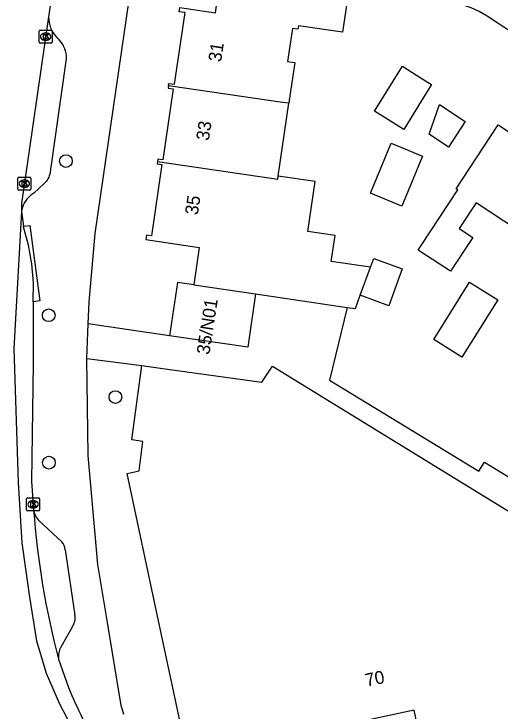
# Model space of a CAD drawing. Extents: x 159280 to 160375, y 384531 to 385872.
# Drawn here: x 159968.6 to 160006.1, y 384621.7 to 384675.4 of the extents above; entities that cross this region are included whole.
import ezdxf

# ---------------------------------------------------------------- set-up
doc = ezdxf.new("R2010")
doc.units = 0
for name, color, linetype in [('IMGEO_Boom', 7, 'Continuous'), ('IMGEO_Kolk', 7, 'Continuous'), ('IMGEO_Pand', 7, 'Continuous'), ('IMGEO_Pand_nummerreeks', 7, 'Continuous'), ('IMGEO_Rijbaan_lokaal_open', 7, 'Continuous'), ('IMGEO_Voetpad_open', 7, 'Continuous')]:
    doc.layers.add(name, color=color, linetype=linetype)

msp = doc.modelspace()

# ---------------------------------------------------------------- linework, layer by layer
at = {"layer": 'IMGEO_Boom'}
for centre in [(159972.645, 384664.044), (159971.323, 384652.191), (159976.457, 384645.896), (159971.332, 384640.849)]:
    msp.add_circle(centre, 0.489, dxfattribs=at)
at = {"layer": 'IMGEO_Kolk'}
for p, q in [((159970.586, 384673.196), (159970.586, 384674.048)), ((159970.661, 384674.122), (159971.513, 384674.122)), ((159971.074, 384673.902), (159971.099, 384673.902)), ((159971.587, 384674.048), (159971.587, 384673.196)), ((159971.097, 384673.342), (159971.072, 384673.342)), ((159971.513, 384673.122), (159970.661, 384673.122)), ((159968.947, 384661.888), (159968.947, 384662.74)), ((159969.022, 384662.814), (159969.874, 384662.814)), ((159969.435, 384662.594), (159969.46, 384662.594)), ((159969.948, 384662.74), (159969.948, 384661.888)), ((159969.874, 384661.814), (159969.022, 384661.814)), ((159969.458, 384662.034), (159969.433, 384662.034)), ((159969.619, 384637.219), (159969.619, 384638.071)), ((159969.694, 384638.145), (159970.546, 384638.145)), ((159970.107, 384637.925), (159970.132, 384637.925)), ((159970.62, 384638.071), (159970.62, 384637.219)), ((159970.546, 384637.145), (159969.694, 384637.145)), ((159970.13, 384637.365), (159970.105, 384637.365))]:
    msp.add_line(p, q, dxfattribs=at)
for points in [[(159970.586, 384673.196), (159970.586, 384674.048)], [(159970.661, 384674.122), (159971.513, 384674.122)], [(159971.587, 384674.048), (159971.587, 384673.196)], [(159970.907, 384673.822), (159971.03, 384673.822), (159971.03, 384673.671), (159971.16, 384673.822), (159971.324, 384673.822), (159971.178, 384673.671), (159971.331, 384673.422), (159971.179, 384673.422), (159971.094, 384673.586), (159971.03, 384673.519), (159971.03, 384673.422), (159970.907, 384673.422), (159970.907, 384673.822)], [(159971.513, 384673.122), (159970.661, 384673.122)], [(159968.947, 384661.888), (159968.947, 384662.74)], [(159969.022, 384662.814), (159969.874, 384662.814)], [(159969.948, 384662.74), (159969.948, 384661.888)], [(159969.268, 384662.514), (159969.391, 384662.514), (159969.391, 384662.363), (159969.521, 384662.514), (159969.685, 384662.514), (159969.539, 384662.363), (159969.692, 384662.114), (159969.54, 384662.114), (159969.455, 384662.278), (159969.391, 384662.211), (159969.391, 384662.114), (159969.268, 384662.114), (159969.268, 384662.514)], [(159969.874, 384661.814), (159969.022, 384661.814)], [(159969.619, 384637.219), (159969.619, 384638.071)], [(159969.694, 384638.145), (159970.546, 384638.145)], [(159970.62, 384638.071), (159970.62, 384637.219)], [(159969.94, 384637.845), (159970.063, 384637.845), (159970.063, 384637.694), (159970.193, 384637.845), (159970.357, 384637.845), (159970.211, 384637.694), (159970.364, 384637.445), (159970.212, 384637.445), (159970.127, 384637.609), (159970.063, 384637.542), (159970.063, 384637.445), (159969.94, 384637.445), (159969.94, 384637.845)], [(159970.546, 384637.145), (159969.694, 384637.145)]]:
    msp.add_lwpolyline(points, dxfattribs=at)
for centre, start, end in [((159970.663, 384674.046), 91.552, 178.448), ((159970.663, 384674.046), 91.552, 178.448), ((159971.511, 384674.046), 1.552, 88.448), ((159971.511, 384674.046), 1.552, 88.448), ((159970.663, 384673.198), 181.552, 268.448), ((159970.663, 384673.198), 181.552, 268.448), ((159971.511, 384673.198), 271.552, 358.448), ((159971.511, 384673.198), 271.552, 358.448), ((159969.024, 384662.738), 91.552, 178.448), ((159969.024, 384662.738), 91.552, 178.448), ((159969.872, 384662.738), 1.552, 88.448), ((159969.872, 384662.738), 1.552, 88.448), ((159969.024, 384661.89), 181.552, 268.448), ((159969.024, 384661.89), 181.552, 268.448), ((159969.872, 384661.89), 271.552, 358.448), ((159969.872, 384661.89), 271.552, 358.448), ((159969.696, 384638.069), 91.552, 178.448), ((159969.696, 384638.069), 91.552, 178.448), ((159970.544, 384638.069), 1.552, 88.448), ((159970.544, 384638.069), 1.552, 88.448), ((159969.696, 384637.221), 181.552, 268.448), ((159969.696, 384637.221), 181.552, 268.448), ((159970.544, 384637.221), 271.552, 358.448), ((159970.544, 384637.221), 271.552, 358.448)]:
    msp.add_arc(centre, 0.0765, start, end, dxfattribs=at)
for centre, major_axis, ratio, start_param, end_param in [((159971.073, 384673.622), (-0.387, 0.002), 0.722429, 4.712389, 7.853982), ((159971.098, 384673.622), (-0.39, 0.002), 0.717154, 1.570796, 4.712389), ((159969.434, 384662.314), (-0.387, 0.002), 0.722429, 4.712389, 7.853982), ((159969.459, 384662.314), (-0.39, 0.002), 0.717154, 1.570796, 4.712389), ((159970.106, 384637.645), (-0.387, 0.002), 0.722429, 4.712389, 7.853982), ((159970.131, 384637.645), (-0.39, 0.002), 0.717154, 1.570796, 4.712389)]:
    msp.add_ellipse(centre, major_axis=major_axis, ratio=ratio, start_param=start_param, end_param=end_param, dxfattribs=at)
at = {"layer": 'IMGEO_Pand'}
for points in [[(159980.544, 384669.845), (159980.57, 384670.023), (159981.011, 384669.958), (159981.816, 384675.472), (159981.365, 384675.538), (159981.412, 384675.862), (159984.161, 384675.46), (159984.655, 384678.84)], [(159994.441, 384677.412), (159993.938, 384673.964), (159990.537, 384674.46), (159990.497, 384674.19), (159990.075, 384674.251), (159989.703, 384671.7), (159990.264, 384671.618), (159989.864, 384668.879), (159989.811, 384668.513)], [(160000, 384668.646), (159998.656, 384666.483), (159996.401, 384667.885), (159998.545, 384671.335), (160000, 384670.43), (160000.8, 384669.933), (160000, 384668.646)], [(159980.544, 384669.845), (159980.518, 384669.663), (159980.911, 384669.606), (159980.112, 384664.133), (159979.715, 384664.191), (159979.689, 384664.015)], [(159989.811, 384668.513), (159989.305, 384668.561), (159980.544, 384669.845)], [(159988.991, 384662.895), (159989.811, 384668.513)], [(160002.095, 384665.124), (160000.602, 384666.105), (160001.403, 384668.402), (160003.391, 384667.095), (160002.095, 384665.124)], [(160008.441, 384658.06), (160004.227, 384660.831), (160002.927, 384658.854), (160003.958, 384658.177), (160002.244, 384655.571), (160000, 384657.047), (159999.772, 384657.197), (160000, 384657.544), (160002.817, 384661.828), (160002.678, 384661.92), (160003.166, 384662.661), (160005.913, 384666.838), (160008.828, 384664.921), (160010.181, 384666.978), (160013.061, 384665.084)], [(159998.497, 384660.591), (159996.09, 384661.585), (159997.675, 384665.424), (160000.082, 384664.43), (159998.497, 384660.591)], [(159979.689, 384664.015), (159979.664, 384663.84), (159980.038, 384663.786), (159979.237, 384658.295), (159978.846, 384658.352), (159978.796, 384658.009), (159982.908, 384657.409), (159982.484, 384654.527)], [(159979.689, 384664.015), (159988.45, 384662.731), (159988.956, 384662.653), (159988.991, 384662.895)], [(159996.093, 384655.883), (159993.067, 384656.324), (159993.359, 384658.324), (159991.266, 384658.629), (159991.828, 384662.482), (159988.991, 384662.895)], [(159996.093, 384655.883), (159996.338, 384656.551), (159998.534, 384655.747), (159997.499, 384652.918), (159995.303, 384653.722)], [(159995.303, 384653.722), (159996.093, 384655.883)], [(159982.484, 384654.527), (159981.227, 384654.712), (159980.624, 384650.612)], [(160003.709, 384654.731), (160005.884, 384653.378), (160003.134, 384648.957), (160000.959, 384650.31), (160003.709, 384654.731)], [(159982.484, 384654.527), (159987.248, 384653.826)], [(159987.248, 384653.826), (159986.645, 384649.726), (159980.624, 384650.612)], [(159987.248, 384653.826), (159994.3, 384652.788)], [(159994.3, 384652.788), (159994.927, 384652.696), (159995.303, 384653.722)], [(160011.237, 384634.358), (160011.297, 384634.075), (160011.515, 384633.037), (160011.69, 384632.205), (160012.697, 384632.417), (160013.12, 384630.406), (160015.037, 384630.809), (160016.519, 384623.743), (160017.106, 384623.869), (160017.988, 384619.767), (160000.666, 384616.097), (160000, 384619.242), (159999.458, 384621.801), (159994.77, 384620.814), (159995.205, 384618.742), (159988.881, 384616.711), (159982.467, 384616.083), (159979.436, 384630.236), (159977.357, 384640.023), (159978.276, 384640.219), (159978.561, 384642.486), (159977.719, 384642.6), (159978.491, 384648.319)], [(159978.491, 384648.319), (159980.462, 384648.046), (159987.733, 384647.039), (159988.557, 384648.274), (160000, 384641.253), (160011.237, 384634.358)]]:
    msp.add_lwpolyline(points, dxfattribs=at)
at = {"layer": 'IMGEO_Rijbaan_lokaal_open'}
for points in [[(159971.827, 384678.621), (159971.743, 384678.16), (159971.729, 384678.051), (159971.306, 384675.134)], [(159971.306, 384675.134), (159969.225, 384660.781), (159969.222, 384660.175)], [(159969.222, 384660.175), (159968.642, 384649.632), (159968.977, 384639.313), (159969.246, 384634.671), (159969.852, 384630.499), (159970.389, 384627.135), (159971.129, 384624.646), (159972.138, 384622.291), (159975.103, 384616.651)], [(159969.222, 384660.175), (159969.371, 384659.033)], [(159970.135, 384653.22), (159970.142, 384654.68), (159970.019, 384656.136), (159969.767, 384657.574), (159969.387, 384658.984), (159969.371, 384659.033)], [(159970.135, 384653.22), (159970.126, 384648.473), (159970.004, 384639.414), (159970.156, 384637.242)], [(159972.081, 384625.744), (159972.832, 384623.548)]]:
    msp.add_lwpolyline(points, dxfattribs=at)
for centre, radius, start, end in [((160032.754, 384641.812), 62.765, 184.17556, 194.83312), ((160024.484, 384645.765), 56.227, 203.2737, 208.6141)]:
    msp.add_arc(centre, radius, start, end, dxfattribs=at)
at = {"layer": 'IMGEO_Voetpad_open'}
for points in [[(159974.36, 384651.534), (159974.433, 384653.199), (159974.901, 384658.477), (159977.914, 384679.304)], [(160051.229, 384644.76), (160005.069, 384675.189), (160004.464, 384675.541), (160003.83, 384675.838), (160003.172, 384676.077), (160002.496, 384676.256), (160001.886, 384676.364), (160000, 384676.629), (159994.441, 384677.412)], [(159971.306, 384675.134), (159971.318, 384674.92), (159971.35, 384674.707), (159971.4, 384674.498), (159971.469, 384674.295), (159971.556, 384674.098), (159971.66, 384673.91), (159971.78, 384673.732), (159971.916, 384673.566), (159972.035, 384673.442), (159972.404, 384672.985), (159972.442, 384672.91), (159972.524, 384672.719), (159972.588, 384672.522), (159972.635, 384672.319), (159972.663, 384672.113), (159972.673, 384671.906), (159971.433, 384663.229), (159971.425, 384663.165), (159971.401, 384663.04), (159971.365, 384662.917), (159971.319, 384662.798), (159971.262, 384662.683), (159971.195, 384662.574), (159971.119, 384662.471), (159971.033, 384662.375), (159970.94, 384662.288), (159970.167, 384661.575), (159970.019, 384661.478), (159969.88, 384661.368), (159969.752, 384661.245), (159969.635, 384661.112), (159969.53, 384660.969), (159969.439, 384660.818), (159969.361, 384660.658), (159969.298, 384660.493), (159969.25, 384660.322), (159969.222, 384660.175)], [(159969.371, 384659.033), (159969.866, 384659.097), (159970.63, 384653.284), (159970.135, 384653.22)], [(159994.3, 384652.788), (159992.944, 384647.204), (159999.309, 384643.315), (160004.437, 384640.182), (160004.872, 384640.894), (160035.102, 384622.424)], [(159974.242, 384648.871), (159974.36, 384651.534)], [(159980.624, 384650.612), (159974.36, 384651.534)], [(159977.1, 384621.472), (159976.896, 384622.169), (159975.845, 384628.562), (159975.107, 384633.026), (159974.353, 384641.387), (159974.242, 384648.871)], [(159974.242, 384648.871), (159978.491, 384648.319)], [(159970.593, 384636.366), (159972.325, 384634.764)], [(159972.583, 384634.153), (159973.324, 384629.122)], [(159973.117, 384628.203), (159972.252, 384626.658)]]:
    msp.add_lwpolyline(points, dxfattribs=at)
for centre, radius, start, end in [((159971.717, 384637.474), 1.578, 188.4466, 224.5788), ((159971.564, 384634.083), 1.021, 3.9419, 41.8428), ((159972.262, 384628.878), 1.089, 321.6835, 12.929), ((159973.779, 384625.899), 1.705, 153.5766, 185.2295)]:
    msp.add_arc(centre, radius, start, end, dxfattribs=at)

# ---------------------------------------------------------------- texts
at = {"layer": 'IMGEO_Pand_nummerreeks'}
for s, rotation, p in [('31', 81.4631, (159984.585, 384671.628)), ('33', 81.4631, (159983.647, 384665.579)), ('35', 81.4631, (159982.788, 384659.853)), ('35/N01', 81.2225, (159983.683, 384649.123)), ('70', 11.8889, (159995.79, 384623.604))]:
    msp.add_text(s, height=1, rotation=rotation, dxfattribs=at).set_placement(p)

doc.saveas('drawing.dxf')
